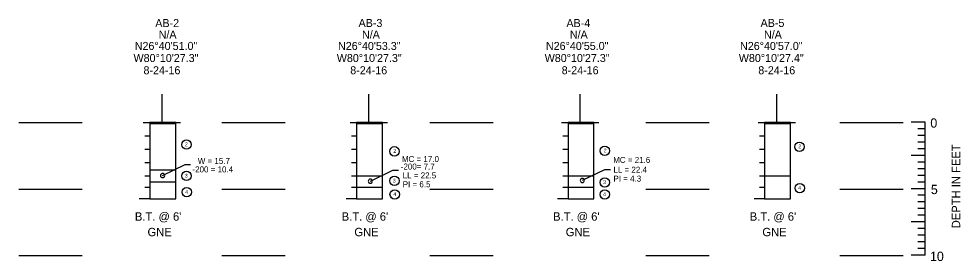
# Model space of a CAD drawing. Extents: x 0 to 331, y -72 to 117.
# Drawn here: x 81.46 to 119.46, y 22.73 to 32.49 of the extents above; entities that cross this region are included whole.
import ezdxf

# ---------------------------------------------------------------- set-up
doc = ezdxf.new("R2010")
doc.units = 0
for name, color, linetype in [('1-BORE', 7, 'Continuous'), ('1-GRID', 7, 'Continuous'), ('1-TEXT', 7, 'Continuous')]:
    doc.layers.add(name, color=color, linetype=linetype)

msp = doc.modelspace()

# ---------------------------------------------------------------- linework, layer by layer
at = {"layer": '1-BORE'}
for p, q in [((86.75, 28.272), (87.795, 28.272)), ((95.097, 28.272), (96.142, 28.272)), ((103.629, 28.272), (104.674, 28.272)), ((111.565, 28.272), (112.61, 28.272)), ((87.266, 26.185), (88.17, 26.625)), ((88.17, 26.625), (88.398, 26.625)), ((86.75, 26.413), (87.795, 26.413)), ((86.75, 26.413), (87.795, 26.413)), ((95.655, 25.958), (96.559, 26.397)), ((96.559, 26.397), (96.787, 26.397)), ((104.208, 25.987), (105.112, 26.427)), ((105.112, 26.427), (105.34, 26.427)), ((86.75, 25.927), (87.795, 25.927)), ((86.75, 25.927), (87.795, 25.927)), ((95.097, 26.17), (96.142, 26.17)), ((95.097, 26.17), (96.142, 26.17)), ((103.629, 26.17), (104.674, 26.17)), ((103.629, 26.17), (104.674, 26.17)), ((111.565, 26.17), (112.61, 26.17)), ((111.565, 26.17), (112.61, 26.17)), ((95.097, 25.707), (96.142, 25.707)), ((95.097, 25.707), (96.142, 25.707)), ((103.629, 25.707), (104.674, 25.707)), ((103.629, 25.707), (104.674, 25.707)), ((86.75, 25.233), (86.322, 25.233)), ((86.75, 25.233), (87.795, 25.233)), ((95.097, 25.233), (94.669, 25.233)), ((95.097, 25.233), (96.142, 25.233)), ((103.629, 25.233), (103.201, 25.233)), ((103.629, 25.233), (104.674, 25.233)), ((111.565, 25.233), (111.137, 25.233)), ((111.565, 25.233), (112.61, 25.233))]:
    msp.add_line(p, q, dxfattribs=at)
for points in [[(87.795, 28.272), (87.795, 28.313), (86.75, 28.313), (86.75, 28.272), (87.795, 28.272), (87.795, 28.272)], [(87.795, 25.233), (87.795, 28.313), (86.75, 28.313), (86.75, 25.233)], [(96.142, 28.272), (96.142, 28.313), (95.097, 28.313), (95.097, 28.272), (96.142, 28.272), (96.142, 28.272)], [(96.142, 25.233), (96.142, 28.313), (95.097, 28.313), (95.097, 25.233)], [(104.674, 28.272), (104.674, 28.313), (103.629, 28.313), (103.629, 28.272), (104.674, 28.272), (104.674, 28.272)], [(104.674, 25.233), (104.674, 28.313), (103.629, 28.313), (103.629, 25.233)], [(112.61, 28.272), (112.61, 28.313), (111.565, 28.313), (111.565, 28.272), (112.61, 28.272), (112.61, 28.272)], [(112.61, 25.233), (112.61, 28.313), (111.565, 28.313), (111.565, 25.233)]]:
    msp.add_lwpolyline(points, dxfattribs=at)
for centre, start, end in [((87.264, 26.178), 0, 180), ((87.264, 26.178), 180, 0), ((95.652, 25.951), 0, 180), ((95.652, 25.951), 180, 0), ((104.205, 25.98), 0, 180), ((104.205, 25.98), 180, 0)]:
    msp.add_arc(centre, 0.0848, start, end, dxfattribs=at)
at = {"layer": '1-GRID'}
for p, q in [((81.462, 28.31), (84.016, 28.31)), ((89.662, 28.31), (92.216, 28.31)), ((98.057, 28.31), (100.611, 28.31)), ((106.773, 28.31), (109.327, 28.31)), ((114.597, 28.31), (117.151, 28.31)), ((118.037, 28.329), (117.473, 28.329)), ((86.545, 27.777), (86.75, 27.777)), ((94.892, 27.777), (95.097, 27.777)), ((103.425, 27.777), (103.629, 27.777)), ((111.361, 27.777), (111.565, 27.777)), ((118.037, 28.061), (117.752, 28.061)), ((118.037, 27.793), (117.752, 27.793)), ((118.037, 27.525), (117.752, 27.525)), ((86.545, 27.242), (86.75, 27.242)), ((94.892, 27.242), (95.097, 27.242)), ((103.425, 27.242), (103.629, 27.242)), ((111.361, 27.242), (111.565, 27.242)), ((118.037, 26.989), (117.473, 26.989)), ((118.037, 26.989), (117.473, 26.989)), ((118.037, 27.257), (117.752, 27.257)), ((86.545, 26.706), (86.75, 26.706)), ((94.892, 26.706), (95.097, 26.706)), ((103.425, 26.706), (103.629, 26.706)), ((111.361, 26.706), (111.565, 26.706)), ((118.037, 26.721), (117.752, 26.721)), ((118.037, 26.453), (117.752, 26.453)), ((86.545, 26.17), (86.75, 26.17)), ((94.892, 26.17), (95.097, 26.17)), ((103.425, 26.17), (103.629, 26.17)), ((111.361, 26.17), (111.565, 26.17)), ((118.037, 26.185), (117.752, 26.185)), ((118.037, 25.917), (117.752, 25.917)), ((81.462, 25.631), (84.016, 25.631)), ((86.545, 25.707), (86.75, 25.707)), ((89.662, 25.631), (92.216, 25.631)), ((94.892, 25.707), (95.097, 25.707)), ((98.057, 25.631), (100.611, 25.631)), ((103.425, 25.707), (103.629, 25.707)), ((106.773, 25.631), (109.327, 25.631)), ((111.361, 25.707), (111.565, 25.707)), ((114.597, 25.631), (117.151, 25.631)), ((118.037, 25.649), (117.473, 25.649)), ((118.037, 25.649), (117.473, 25.649)), ((86.75, 25.233), (86.955, 25.233)), ((95.097, 25.233), (95.302, 25.233)), ((103.629, 25.233), (103.834, 25.233)), ((111.565, 25.233), (111.77, 25.233)), ((118.037, 25.381), (117.752, 25.381)), ((118.037, 25.113), (117.752, 25.113)), ((118.037, 24.845), (117.752, 24.845)), ((118.037, 24.578), (117.752, 24.578)), ((118.037, 24.31), (117.473, 24.31)), ((118.037, 24.31), (117.473, 24.31)), ((118.037, 24.042), (117.752, 24.042)), ((118.037, 23.774), (117.752, 23.774)), ((118.037, 23.506), (117.752, 23.506)), ((118.037, 23.238), (117.752, 23.238)), ((81.462, 22.952), (84.016, 22.952)), ((89.662, 22.952), (92.216, 22.952)), ((98.057, 22.952), (100.611, 22.952)), ((106.773, 22.952), (109.327, 22.952)), ((114.597, 22.952), (117.151, 22.952)), ((118.037, 22.97), (117.473, 22.97))]:
    msp.add_line(p, q, dxfattribs=at)
for points in [[(118.037, 25.649), (118.037, 28.329)], [(118.037, 22.97), (118.037, 25.649)]]:
    msp.add_lwpolyline(points, dxfattribs=at)
at = {"layer": '1-TEXT'}
for p, q in [((87.23, 29.464), (87.23, 28.313)), ((95.577, 29.464), (95.577, 28.313)), ((104.109, 29.464), (104.109, 28.313)), ((112.045, 29.464), (112.045, 28.313))]:
    msp.add_line(p, q, dxfattribs=at)
for points in [[(86.484, 28.313), (87.993, 28.313)], [(94.83, 28.313), (96.339, 28.313)], [(103.363, 28.313), (104.872, 28.313)], [(111.299, 28.313), (112.808, 28.313)]]:
    msp.add_lwpolyline(points, dxfattribs=at)
for centre in [(88.23, 27.426), (105.113, 27.177), (112.969, 27.338), (96.622, 27.154), (88.23, 26.163), (96.622, 25.965), (105.113, 25.902), (112.983, 25.671), (88.241, 25.509), (96.633, 25.416), (105.113, 25.417)]:
    msp.add_circle(centre, 0.19, dxfattribs=at)

# ---------------------------------------------------------------- texts
at = {"layer": '1-GRID'}
for s, height, p in [('0', 0.375, (118.252, 28.109)), ('5', 0.375, (118.275, 25.429)), ('10', 0.3751, (118.238, 22.733))]:
    msp.add_text(s, height=height, dxfattribs=at).set_placement(p)
msp.add_text('DEPTH IN FEET', height=0.3376, rotation=90, dxfattribs=at).set_placement((119.457, 24.052))
at = {"layer": '1-TEXT'}
for s, height, p in [('AB-2', 0.3231, (86.97, 32.164)), ('AB-3', 0.3231, (95.175, 32.167)), ('AB-4', 0.3231, (103.565, 32.164)), ('AB-5', 0.3231, (111.401, 32.168)), ('N/A', 0.3231, (87.108, 31.701)), ('N/A', 0.3231, (95.313, 31.701)), ('N/A', 0.3231, (103.703, 31.701)), ('N/A', 0.3231, (111.539, 31.701)), ('N26%%D40\'51.0"', 0.32313, (86.142, 31.241)), ('N26%%D40\'53.3"', 0.32313, (94.346, 31.241)), ('N26%%D40\'55.0"', 0.32313, (102.737, 31.241)), ('N26%%D40\'57.0"', 0.32313, (110.572, 31.241)), ('W80%%D10\'27.3"', 0.32313, (86.092, 30.755)), ('W80%%D10\'27.3"', 0.32313, (94.296, 30.755)), ('W80%%D10\'27.3"', 0.32313, (102.687, 30.755)), ('W80%%D10\'27.4"', 0.32313, (110.522, 30.755)), ('8-24-16', 0.3231, (86.494, 30.261)), ('8-24-16', 0.3231, (94.84, 30.261)), ('8-24-16', 0.3231, (103.373, 30.261)), ('8-24-16', 0.3231, (111.309, 30.261)), ('2', 0.152, (88.162, 27.358)), ('2', 0.152, (112.923, 27.276)), ('2', 0.152, (96.576, 27.092)), ('2', 0.152, (105.067, 27.114)), ('W = 15.7', 0.2411, (88.686, 26.648)), ('-200= 7.7', 0.2411, (96.879, 26.421)), ('MC = 17.0', 0.2411, (96.924, 26.722)), ('MC = 21.6', 0.2411, (105.452, 26.688)), ('3', 0.152, (88.162, 26.095)), ('-200 = 10.4', 0.24114, (88.471, 26.305)), ('LL = 22.5', 0.2411, (96.957, 26.063)), ('LL = 22.4', 0.2411, (105.462, 26.293)), ('3', 0.152, (96.554, 25.897)), ('PI = 6.5', 0.2411, (96.957, 25.705)), ('3', 0.152, (105.044, 25.834)), ('PI = 4.3', 0.2411, (105.462, 25.935)), ('4', 0.152, (88.173, 25.44)), ('4', 0.152, (96.576, 25.354)), ('4', 0.152, (105.044, 25.349)), ('4', 0.152, (112.915, 25.603)), ("B.T. @ 6'", 0.3376, (86.148, 24.358)), ("B.T. @ 6'", 0.3376, (94.495, 24.358)), ("B.T. @ 6'", 0.3376, (103.027, 24.358)), ("B.T. @ 6'", 0.3376, (110.963, 24.358)), ('GNE', 0.3376, (86.657, 23.731)), ('GNE', 0.3376, (95.004, 23.731)), ('GNE', 0.3376, (103.537, 23.731)), ('GNE', 0.3376, (111.473, 23.731))]:
    msp.add_text(s, height=height, dxfattribs=at).set_placement(p)

doc.saveas('drawing.dxf')
